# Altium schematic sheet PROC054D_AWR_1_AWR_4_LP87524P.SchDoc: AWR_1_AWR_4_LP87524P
size 558 x 431 mm; Date: Not shown in title block; ApprovedBy: Not shown in title block; CheckedBy: Not shown in title block; Author: Not shown in title block; CompanyName: Not shown in title block; DrawnBy: a0271760; Engineer: Not shown in title block; Organization: Not shown in title block; Address1: Not shown in title block; Address2: Not shown in title block; Address3: Not shown in title block; Address4: Not shown in title block; DocumentNumber: 4; Revision: Use project pAWRameter SCH_Rev; SheetNumber: 4; SheetTotal: 19; PageSetup: Record=PageOptions¦CenterHorizontal=True¦CenterVertical=True¦PrintScale=1.00¦XCorrection=1.00¦YCorrection=1.00¦PrintKind=0¦BorderSize=5000000¦LeftOffset=0¦BottomOffset=0¦Orientation=2¦PaperLength=1000¦PaperWidth=1000¦Scale=100¦PaperSource=15¦PrintQuality=600¦MediaType=1¦DitherType=10¦PaperKind=Letter¦PrintScaleMode=1
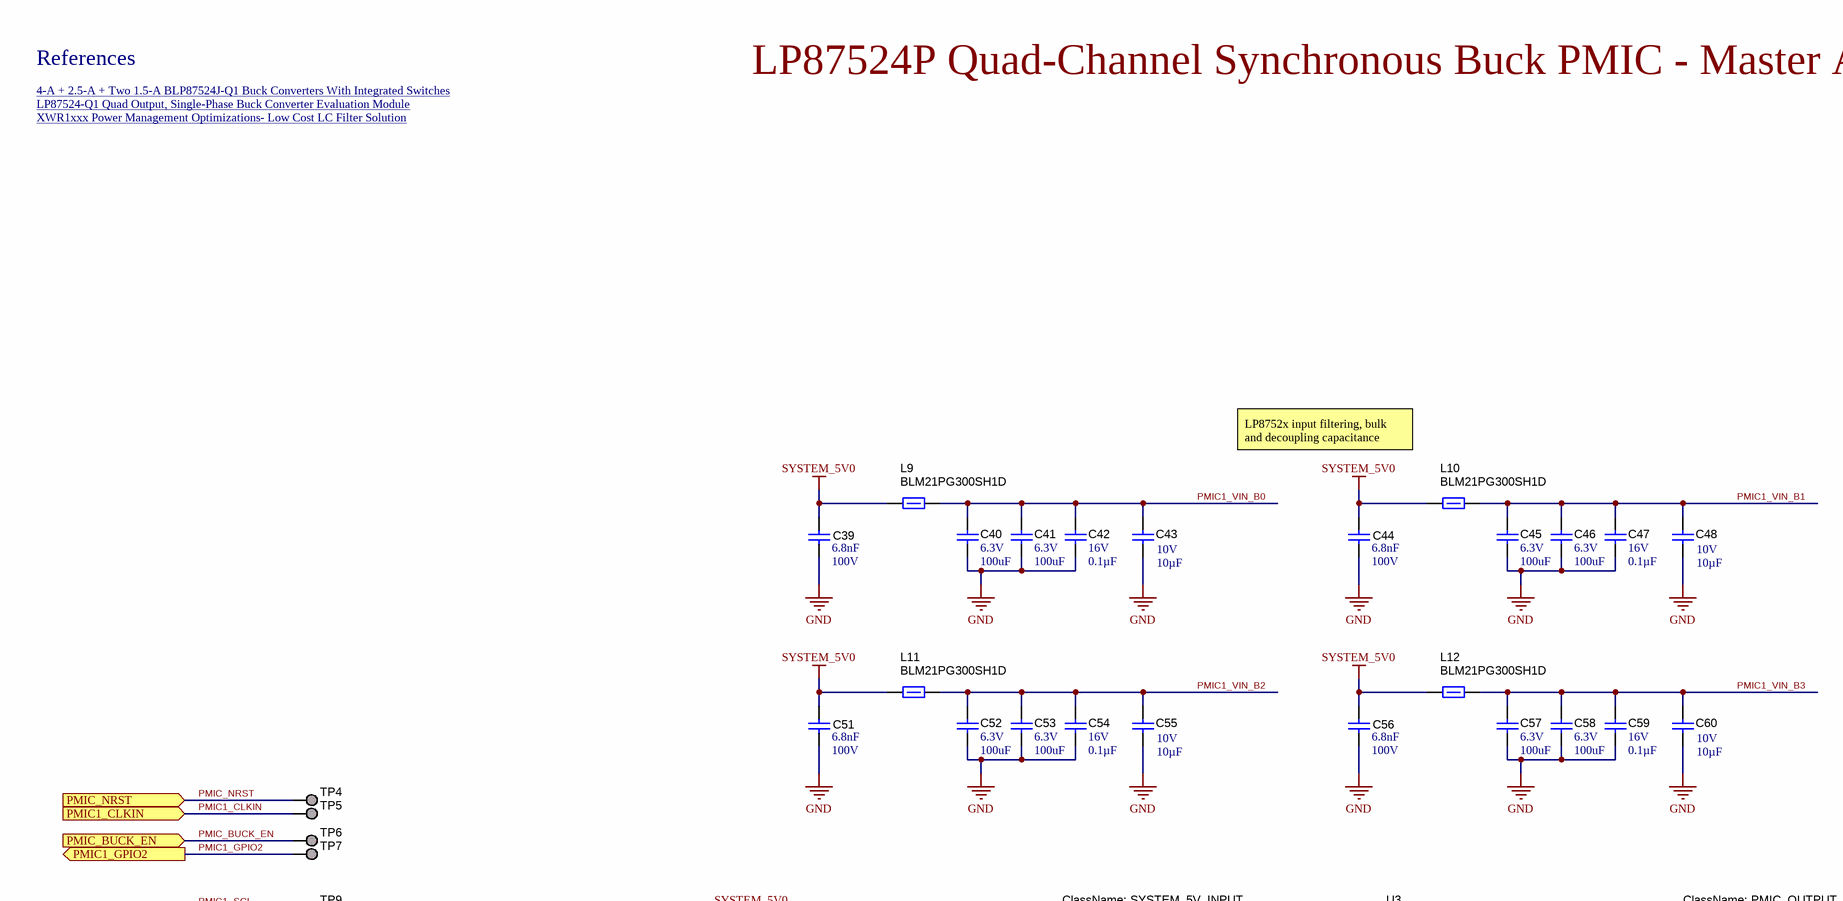
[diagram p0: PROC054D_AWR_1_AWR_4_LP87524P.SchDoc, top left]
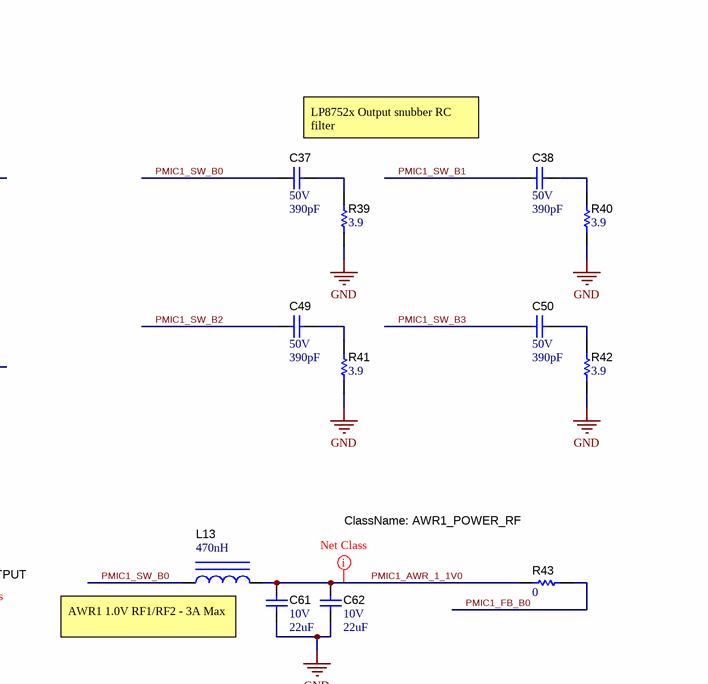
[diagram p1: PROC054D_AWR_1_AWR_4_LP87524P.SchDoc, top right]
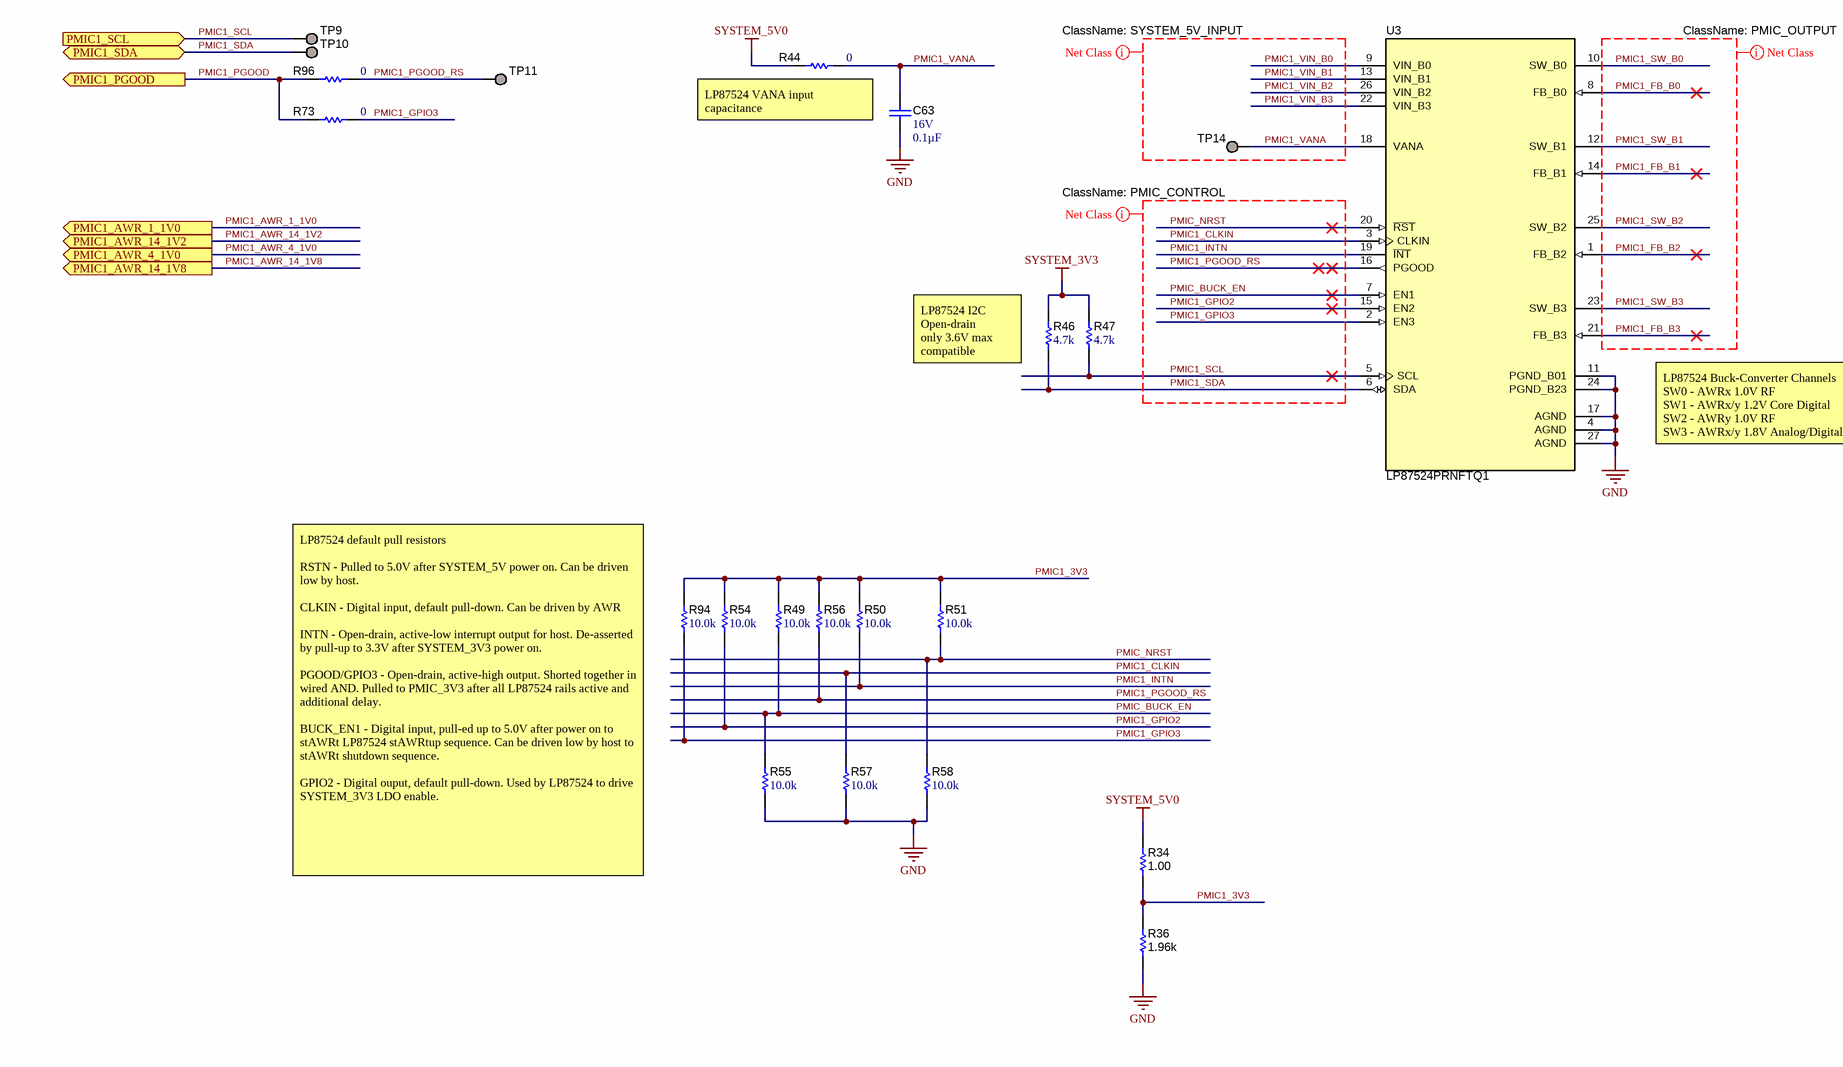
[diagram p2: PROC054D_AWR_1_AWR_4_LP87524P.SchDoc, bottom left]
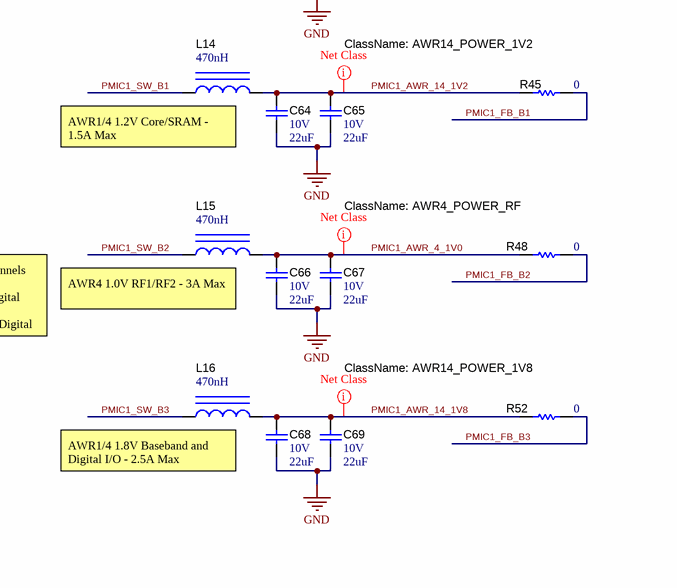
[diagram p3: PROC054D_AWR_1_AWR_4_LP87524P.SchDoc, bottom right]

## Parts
C37  VDC_V: 50V  ValueDisplayed: 390pF  [0402S]  (hidden comment: GCM155R71H391KA37D)
C38  VDC_V: 50V  ValueDisplayed: 390pF  [0402S]  (hidden comment: GCM155R71H391KA37D)
C39  Cap_F: 6.8nF  VDC_V: 100V  [0603S]  (hidden comment: GCM188R72A682KA37D)
C40  VDC_V: 6.3V  ValueDisplayed: 100uF  [0805L]  (hidden comment: GRM21BR60J107M)
C41  VDC_V: 6.3V  ValueDisplayed: 100uF  [0805L]  (hidden comment: GRM21BR60J107M)
C42  VDC_V: 16V  ValueDisplayed: 0.1µF  [0402S]  (hidden comment: GCM155R71C104JA55D)
C43  Cap_F: 10µF  VDC_V: 10V  [0805L]  (hidden comment: GRM21BR71A106KA73L)
C44  Cap_F: 6.8nF  VDC_V: 100V  [0603S]  (hidden comment: GCM188R72A682KA37D)
C45  VDC_V: 6.3V  ValueDisplayed: 100uF  [0805L]  (hidden comment: GRM21BR60J107M)
C46  VDC_V: 6.3V  ValueDisplayed: 100uF  [0805L]  (hidden comment: GRM21BR60J107M)
C47  VDC_V: 16V  ValueDisplayed: 0.1µF  [0402S]  (hidden comment: GCM155R71C104JA55D)
C48  Cap_F: 10µF  VDC_V: 10V  [0805L]  (hidden comment: GRM21BR71A106KA73L)
C49  VDC_V: 50V  ValueDisplayed: 390pF  [0402S]  (hidden comment: GCM155R71H391KA37D)
C50  VDC_V: 50V  ValueDisplayed: 390pF  [0402S]  (hidden comment: GCM155R71H391KA37D)
C51  Cap_F: 6.8nF  VDC_V: 100V  [0603S]  (hidden comment: GCM188R72A682KA37D)
C52  VDC_V: 6.3V  ValueDisplayed: 100uF  [0805L]  (hidden comment: GRM21BR60J107M)
C53  VDC_V: 6.3V  ValueDisplayed: 100uF  [0805L]  (hidden comment: GRM21BR60J107M)
C54  VDC_V: 16V  ValueDisplayed: 0.1µF  [0402S]  (hidden comment: GCM155R71C104JA55D)
C55  Cap_F: 10µF  VDC_V: 10V  [0805L]  (hidden comment: GRM21BR71A106KA73L)
C56  Cap_F: 6.8nF  VDC_V: 100V  [0603S]  (hidden comment: GCM188R72A682KA37D)
C57  VDC_V: 6.3V  ValueDisplayed: 100uF  [0805L]  (hidden comment: GRM21BR60J107M)
C58  VDC_V: 6.3V  ValueDisplayed: 100uF  [0805L]  (hidden comment: GRM21BR60J107M)
C59  VDC_V: 16V  ValueDisplayed: 0.1µF  [0402S]  (hidden comment: GCM155R71C104JA55D)
C60  Cap_F: 10µF  VDC_V: 10V  [0805L]  (hidden comment: GRM21BR71A106KA73L)
C61  VDC_V: 10V  ValueDisplayed: 22uF  [0805L]  (hidden comment: C2012X7S1A226M125AC)
C62  VDC_V: 10V  ValueDisplayed: 22uF  [0805L]  (hidden comment: C2012X7S1A226M125AC)
C63  VDC_V: 16V  ValueDisplayed: 0.1µF  [0402S]  (hidden comment: GCM155R71C104JA55D)
C64  VDC_V: 10V  ValueDisplayed: 22uF  [0805L]  (hidden comment: C2012X7S1A226M125AC)
C65  VDC_V: 10V  ValueDisplayed: 22uF  [0805L]  (hidden comment: C2012X7S1A226M125AC)
C66  VDC_V: 10V  ValueDisplayed: 22uF  [0805L]  (hidden comment: C2012X7S1A226M125AC)
C67  VDC_V: 10V  ValueDisplayed: 22uF  [0805L]  (hidden comment: C2012X7S1A226M125AC)
C68  VDC_V: 10V  ValueDisplayed: 22uF  [0805L]  (hidden comment: C2012X7S1A226M125AC)
C69  VDC_V: 10V  ValueDisplayed: 22uF  [0805L]  (hidden comment: C2012X7S1A226M125AC)
L9  BLM21PG300SH1D  [0805_HV]
L10  BLM21PG300SH1D  [0805_HV]
L11  BLM21PG300SH1D  [0805_HV]
L12  BLM21PG300SH1D  [0805_HV]
L13  ValueDisplayed: 470nH  [DFE252012P]  (hidden comment: DFE252012PD-R47M)
L14  ValueDisplayed: 470nH  [DFE252012P]  (hidden comment: DFE252012PD-R47M)
L15  ValueDisplayed: 470nH  [DFE252012P]  (hidden comment: DFE252012PD-R47M)
L16  ValueDisplayed: 470nH  [DFE252012P]  (hidden comment: DFE252012PD-R47M)
R34  ValueDisplayed: 1.00  [0603]  (hidden comment: CRCW06031R00FKEA)
R36  ValueDisplayed: 1.96k  [0603]  (hidden comment: CRCW06031K96FKEA)
R39  ValueDisplayed: 3.9  [0402S]  (hidden comment: CRCW04023R90JNED)
R40  ValueDisplayed: 3.9  [0402S]  (hidden comment: CRCW04023R90JNED)
R41  ValueDisplayed: 3.9  [0402S]  (hidden comment: CRCW04023R90JNED)
R42  ValueDisplayed: 3.9  [0402S]  (hidden comment: CRCW04023R90JNED)
R43  ValueDisplayed: 0  [0402S]  (hidden comment: CRCW04020000Z0ED)
R44  ValueDisplayed: 0  [0603S]  (hidden comment: MCT06030Z0000ZP500)
R45  ValueDisplayed: 0  [0402S]  (hidden comment: CRCW04020000Z0ED)
R46  ValueDisplayed: 4.7k  [0402]  (hidden comment: CRCW04024K70JNED)
R47  ValueDisplayed: 4.7k  [0402]  (hidden comment: CRCW04024K70JNED)
R48  ValueDisplayed: 0  [0402S]  (hidden comment: CRCW04020000Z0ED)
R49  ValueDisplayed: 10.0k  [0402]  (hidden comment: CRCW040210K0FKED)
R50  ValueDisplayed: 10.0k  [0402]  (hidden comment: CRCW040210K0FKED)
R51  ValueDisplayed: 10.0k  [0402]  (hidden comment: CRCW040210K0FKED)
R52  ValueDisplayed: 0  [0402S]  (hidden comment: CRCW04020000Z0ED)
R54  ValueDisplayed: 10.0k  [0402]  (hidden comment: CRCW040210K0FKED)
R55  ValueDisplayed: 10.0k  [0402]  (hidden comment: CRCW040210K0FKED)
R56  ValueDisplayed: 10.0k  [0402]  (hidden comment: CRCW040210K0FKED)
R57  ValueDisplayed: 10.0k  [0402]  (hidden comment: CRCW040210K0FKED)
R58  ValueDisplayed: 10.0k  [0402]  (hidden comment: CRCW040210K0FKED)
R73  ValueDisplayed: 0  [0603]  (hidden comment: MCT06030Z0000ZP500)
R94  ValueDisplayed: 10.0k  [0402]  (hidden comment: CRCW040210K0FKED)
R96  ValueDisplayed: 0  [0603]  (hidden comment: MCT06030Z0000ZP500)
TP4  TP_SM_1MM  [TP_SM_1MM]  (value not drawn)  (no BOM)
TP5  TP_SM_1MM  [TP_SM_1MM]  (value not drawn)  (no BOM)
TP6  TP_SM_1MM  [TP_SM_1MM]  (value not drawn)  (no BOM)
TP7  TP_SM_1MM  [TP_SM_1MM]  (value not drawn)  (no BOM)
TP9  TP_SM_1MM  [TP_SM_1MM]  (value not drawn)  (no BOM)
TP10  TP_SM_1MM  [TP_SM_1MM]  (value not drawn)  (no BOM)
TP11  TP_SM_1MM  [TP_SM_1MM]  (value not drawn)  (no BOM)
TP14  TP_SM_1MM  [TP_SM_1MM]  (value not drawn)  (no BOM)
U3  LP87524PRNFTQ1  [RNF0026C]

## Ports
PMIC1_AWR_1_1V0 (out), PMIC1_AWR_4_1V0 (out), PMIC1_AWR_14_1V2 (out), PMIC1_AWR_14_1V8 (out), PMIC1_CLKIN (in), PMIC1_GPIO2 (out), PMIC1_PGOOD (out), PMIC1_SCL (in), PMIC1_SDA (bidir), PMIC_BUCK_EN (in), PMIC_NRST (in)

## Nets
GND: C39.2 C40.2 C41.2 C42.2 C43.2 C44.2 C45.2 C46.2 C47.2 C48.2 C51.2 C52.2 C53.2 C54.2 C55.2 C56.2 C57.2 C58.2 C59.2 C60.2 C61.2 C62.2 C63.2 C64.2 C65.2 C66.2 C67.2 C68.2 C69.2 R36.1 R39.1 R40.1 R41.1 R42.1 R55.1 R57.1 R58.1 U3.4(AGND) U3.11(PGND_B01) U3.17(AGND) U3.24(PGND_B23) U3.27(AGND)
SYSTEM_3V3: R46.1 R47.2
SYSTEM_5V0: C39.1 C44.1 C51.1 C56.1 L9.1 L10.1 L11.1 L12.1 R34.2 R44.1
PMIC1_3V3: R34.1 R36.2 R49.2 R50.2 R51.2 R54.2 R56.2 R94.2
PMIC1_AWR_1_1V0: C61.1 C62.1 L13.2 R43.1 ; port PMIC1_AWR_1_1V0
PMIC1_AWR_4_1V0: C66.1 C67.1 L15.2 R48.1 ; port PMIC1_AWR_4_1V0
PMIC1_AWR_14_1V2: C64.1 C65.1 L14.2 R45.1 ; port PMIC1_AWR_14_1V2
PMIC1_AWR_14_1V8: C68.1 C69.1 L16.2 R52.1 ; port PMIC1_AWR_14_1V8
PMIC1_CLKIN: R57.2 TP5.1 U3.3(CLKIN) ; port PMIC1_CLKIN
PMIC1_FB_B0: R43.2 U3.8(FB_B0)
PMIC1_FB_B1: R45.2 U3.14(FB_B1)
PMIC1_FB_B2: R48.2 U3.1(FB_B2)
PMIC1_FB_B3: R52.2 U3.21(FB_B3)
PMIC1_GPIO2: R54.1 TP7.1 U3.15(EN2) ; port PMIC1_GPIO2
PMIC1_GPIO3: R73.2 R94.1 U3.2(EN3)
PMIC1_INTN: R50.1 U3.19(~{INT})
PMIC1_PGOOD: R73.1 R96.1 ; port PMIC1_PGOOD
PMIC1_PGOOD_RS: R56.1 R96.2 TP11.1 U3.16(PGOOD)
PMIC1_SCL: R47.1 TP9.1 U3.5(SCL) ; port PMIC1_SCL
PMIC1_SDA: R46.2 TP10.1 U3.6(SDA) ; port PMIC1_SDA
PMIC1_SW_B0: C37.1 L13.1 U3.10(SW_B0)
PMIC1_SW_B1: C38.1 L14.1 U3.12(SW_B1)
PMIC1_SW_B2: C49.1 L15.1 U3.25(SW_B2)
PMIC1_SW_B3: C50.1 L16.1 U3.23(SW_B3)
PMIC1_VANA: C63.1 R44.2 TP14.1 U3.18(VANA)
PMIC1_VIN_B0: C40.1 C41.1 C42.1 C43.1 L9.2 U3.9(VIN_B0)
PMIC1_VIN_B1: C45.1 C46.1 C47.1 C48.1 L10.2 U3.13(VIN_B1)
PMIC1_VIN_B2: C52.1 C53.1 C54.1 C55.1 L11.2 U3.26(VIN_B2)
PMIC1_VIN_B3: C57.1 C58.1 C59.1 C60.1 L12.2 U3.22(VIN_B3)
PMIC_BUCK_EN: R49.1 R55.2 TP6.1 U3.7(EN1) ; port PMIC_BUCK_EN
PMIC_NRST: R51.1 R58.2 TP4.1 U3.20(~{RST}) ; port PMIC_NRST
NetC37_2: C37.2 R39.2
NetC38_2: C38.2 R40.2
NetC49_2: C49.2 R41.2
NetC50_2: C50.2 R42.2

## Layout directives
net class SYSTEM_5V_INPUT: PMIC1_VANA, PMIC1_VIN_B0, PMIC1_VIN_B1, PMIC1_VIN_B2, PMIC1_VIN_B3
net class PMIC_CONTROL: PMIC1_CLKIN, PMIC1_GPIO2, PMIC1_GPIO3, PMIC1_INTN, PMIC1_PGOOD_RS, PMIC1_SCL, PMIC1_SDA, PMIC_BUCK_EN, PMIC_NRST
net class PMIC_OUTPUT: PMIC1_FB_B0, PMIC1_FB_B1, PMIC1_FB_B2, PMIC1_FB_B3, PMIC1_SW_B0, PMIC1_SW_B1, PMIC1_SW_B2, PMIC1_SW_B3
net class AWR14_POWER_1V2: PMIC1_AWR_14_1V2
net class AWR14_POWER_1V8: PMIC1_AWR_14_1V8
net class AWR1_POWER_RF: PMIC1_AWR_1_1V0
net class AWR4_POWER_RF: PMIC1_AWR_4_1V0

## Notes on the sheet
- References
- LP87524P Quad-Channel Synchronous Buck PMIC - Master AWR_1 and Slave AWR_4
- LP87524-Q1 Quad Output, Single-Phase Buck Converter Evaluation Module <http://www.ti.com/tool/lp87524q1evm>
- XWR1xxx Power Management Optimizations- Low Cost LC Filter Solution <http://www.ti.com/lit/pdf/swra577>
- 4-A + 2.5-A + Two 1.5-A BLP87524J-Q1 Buck Converters With Integrated Switches <http://www.ti.com/product/lp87524j-q1>
- LP8752x input filtering, bulk and decoupling capacitance
- (near C37) LP8752x Output snubber RC filter
- (near L13) AWR1 1.0V RF1/RF2 - 3A Max
- (near R44) LP87524 VANA input capacitance
- (near L14) AWR1/4 1.2V Core/SRAM - 1.5A Max
- (near R46) LP87524 I2C
  Open-drain
  only 3.6V max compatible
- (near L15) AWR4 1.0V RF1/RF2 - 3A Max
- LP87524 Buck-Converter Channels
  SW0 - AWRx 1.0V RF
  SW1 - AWRx/y 1.2V Core Digital
  SW2 - AWRy 1.0V RF
  SW3 - AWRx/y 1.8V Analog/Digital
- (near L16) AWR1/4 1.8V Baseband and Digital I/O - 2.5A Max
- (near R94) LP87524 default pull resistors
  RSTN - Pulled to 5.0V after SYSTEM_5V power on. Can be driven low by host.
  CLKIN - Digital input, default pull-down. Can be driven by AWR
  INTN - Open-drain, active-low interrupt output for host. De-asserted by pull-up to 3.3V after SYSTEM_3V3 power on.
  PGOOD/GPIO3 - Open-drain, active-high output. Shorted together in wired AND. Pulled to PMIC_3V3 after all LP87524 rails active and additional delay.
  BUCK_EN1 - Digital input, pull-ed up to 5.0V after power on to stAWRt LP87524 stAWRtup sequence. Can be driven low by host to stAWRt shutdown sequence.
  GPIO2 - Digital ouput, default pull-down. Used by LP87524 to drive SYSTEM_3V3 LDO enable.

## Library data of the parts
C37 C38 C49 C50 = CMP-0080703-2: CAP, CERM, 390 pF, 50 V,+/- 10%, X7R, AEC-Q200 Grade 1, 0402; Manufacturer: MuRata; Cap_Case: 0402; SizeX_mm: 1; SizeZ_mm: 0.6; SizeY_mm: 0.5; AEC Qualified: Y; Value: 390pF; Polarized: N; AEC Category: Q200; TaMax_C: 125°C; TaMin_C: -55°C; SizeAreaWB_mm2: 3; U/M: EA
C39 C44 C51 C56 = CMP-0860888-1: CAP, CERM, 6800 pF, 100 V,+/- 10%, X7R, AEC-Q200 Grade 1, 0603; Manufacturer: MuRata; AEC Grade: 1; AEC Qualified: Y; TaMin_C: -55°C; AEC Category: Q200; SizeY_mm: 0.8; Cap_Case: 0603; ValueDisplayed: 6800pF; Polarized: N; SizeArea_mm2: 1.28; U/M: EA; SizeX_mm: 1.6; SizeAreaWB_mm2: 4.68; TaMax_C: 125°C; Value: 6800pF
C40 C41 = CMP-0008280-2: CAP, CERM, 100 uF, 6.3 V, +/- 20%, X5R, 0805; Manufacturer: MuRata; TaMin_C: -55°C; Polarized: N; SizeAreaWB_mm2: 6.75; Value1: Unknown; U/M: EA; Value: 100uF; TaMax_C: 85°C; SizeZ_mm: 1.45; SizeX_mm: 2; SizeY_mm: 1.25; Cap_Case: 0805; SizeArea_mm2: 2.5; CompType: Capacitor; Cap_F: 100µF; AEC Category: Q200
C42 C63 = CMP-0080702-1: CAP, CERM, 0.1 µF, 16 V,+/- 5%, X7R, AEC-Q200 Grade 1, 0402; Manufacturer: MuRata; Cap_F: 100nF; SizeAreaWB_mm2: 3; SizeArea_mm2: 0.5; AEC Qualified: Y; AEC Category: Q200; Value: 0.1uF; TaMax_C: 125°C; SizeZ_mm: 0.6; AEC Grade: 1; Polarized: N; TaMin_C: -55°C; U/M: EA; CompType: Capacitor; Cap_Case: 0402
C43 C48 C55 C60 = CMP-0081849-1: CAP, CERM, 10 µF,  V,+/- 10%, X7R, 0805; Manufacturer: MuRata; TaMin_C: -55°C; Polarized: N; Green_Lifecycle: Active; SizeAreaWB_mm2: 6.75; Green_REACh: Passed; U/M: EA; Value: 10uF; TaMax_C: 125°C; SizeZ_mm: 1.45; SizeX_mm: 2; SizeY_mm: 1.25; Cap_Case: 0805; SizeArea_mm2: 2.5; AEC Category: Q200
C45 C46 C52 C53 C57 C58 = CMP-0008280-2: CAP, CERM, 100 uF, 6.3 V, +/- 20%, X5R, 0805; Manufacturer: MuRata; TaMin_C: -55°C; Polarized: N; SizeAreaWB_mm2: 6.75; Value1: Unknown; U/M: EA; Value: 100uF; TaMax_C: 85°C; SizeZ_mm: 1.45; SizeX_mm: 2; SizeY_mm: 1.25; Cap_Case: 0805; SizeArea_mm2: 2.5; Cap_F: 100µF; AEC Category: Q200
C47 C54 C59 = CMP-0080702-1: CAP, CERM, 0.1 µF, 16 V,+/- 5%, X7R, AEC-Q200 Grade 1, 0402; Manufacturer: MuRata; Cap_F: 100nF; SizeAreaWB_mm2: 3; SizeArea_mm2: 0.5; AEC Qualified: Y; AEC Category: Q200; Value: 0.1uF; TaMax_C: 125°C; SizeZ_mm: 0.6; AEC Grade: 1; Polarized: N; TaMin_C: -55°C; U/M: EA; Cap_Case: 0402
C61 C62 C64-C69 = CMP-0007890-1: CAP, CERM, 22 uF, 10 V, +/- 20%, X7S, 0805; Manufacturer: TDK; TaMin_C: -55°C; ESR_ohm: 2.05m; Polarized: N; SizeAreaWB_mm2: 6.75; Value1: 0.00205 ohm; U/M: EA; Value: 22uF; TaMax_C: 125°C; SizeZ_mm: 1.45; SizeX_mm: 2; SizeY_mm: 1.25; Cap_Case: 0805; SizeArea_mm2: 2.5; Cap_F: 22µF; IRMS_A: 4.5559A; AEC Category: Q200
L9-L12 = CMP-0003364-1: Ferrite Bead, 30 ohm @ 100 MHz, 4 A, 0805; Manufacturer: MuRata; ZTyp@100MHz_Ohm: 30; SizeAreaWB_mm2: 6.75; DCR_ohm: 0.014; Value1: 0.014 ohm; Value: 30 ohm; Imax_A: 4A; SizeZ_mm: 1.45; SizeX_mm: 2; SizeY_mm: 1.25; SizeArea_mm2: 2.5
L13-L16 = CMP-0058944-1: Inductor, Shielded, 470 nH, 4.7 A, 0.021 ohm, SMD; Manufacturer: MuRata Toko; Isat: 6.1A @ 30% inductance drop; Irms: 4.7A @ 40C rise; SizeAreaWB_mm2: 10.5; DCR_ohm: 0.021; Value: 470nH; Imax_A: 4.7A; SizeZ_mm: 1.2; SizeX_mm: 2.5; SizeY_mm: 2; SizeArea_mm2: 5; AEC Category: Q200
R34 = CMP-0022170-4: RES, 1.00, 1%, 0.1 W, AEC-Q200 Grade 0, 0603; Manufacturer: Vishay-Dale; Power_W: 100mW; TempCo: 100 ppm/C; Value_Code: 1R00; Value: 1.00; EIA_Code: E96; Res_ohm: 1; SizeX_mm: 1.6; SizeY_mm: 0.8; Value2: 0.1W; SizeArea_mm2: 1.28; AEC Qualified: Y; VDC_V: 75V; AEC Category: Q200; AEC Grade: 0
R36 = CMP-0022137-4: RES, 1.96 k, 1%, 0.1 W, AEC-Q200 Grade 0, 0603; Manufacturer: Vishay-Dale; Power_W: 100mW; TempCo: 100 ppm/C; Value_Code: 1k96; Value: 1.96k; EIA_Code: E96; SizeX_mm: 1.6; SizeY_mm: 0.8; SizeZ_mm: 1; Value2: 0.1W; SizeArea_mm2: 1.28; AEC Qualified: Y; VDC_V: 75V; AEC Category: Q200; AEC Grade: 0
R39 = CMP-0026928-3: RES, 3.9, 5%, 0.063 W, AEC-Q200 Grade 0, 0402; Manufacturer: Vishay-Dale; Power_W: 63mW; TempCo: 200 ppm/C; Value_Code: 3R90; Value: 3.9; EIA_Code: E24; SizeX_mm: 1; SizeY_mm: 0.5; SizeZ_mm: 0.6; Value2: 0.063W; CompType: Resistor; AEC Qualified: Y; VDC_V: 50V; AEC Category: Q200; AEC Grade: 0
R40-R42 = CMP-0026928-3: RES, 3.9, 5%, 0.063 W, AEC-Q200 Grade 0, 0402; Manufacturer: Vishay-Dale; Power_W: 63mW; TempCo: 200 ppm/C; Value_Code: 3R90; Value: 3.9; EIA_Code: E24; SizeX_mm: 1; SizeY_mm: 0.5; SizeZ_mm: 0.6; Value2: 0.063W; AEC Qualified: Y; VDC_V: 50V; AEC Category: Q200; AEC Grade: 0
R43 R45 R48 R52 = CMP-0026822-3: RES, 0, 5%, 0.063 W, AEC-Q200 Grade 0, 0402; Manufacturer: Vishay-Dale; Power_W: 63mW; TempCo: 200 ppm/C; Value_Code: 0000; Value: 0; EIA_Code: E24; SizeX_mm: 1; SizeY_mm: 0.5; SizeZ_mm: 0.6; Value2: 0.063W; AEC Qualified: Y; VDC_V: 50V; AEC Category: Q200
R44 = CMP-0025884-3: RES, 0, 5%, 0.125 W, 0603; Manufacturer: Vishay/Beyschlag; Power_W: 125mW; TempCo: ppm/C; Value_Code: 0000; U/M: EA; Value: 0; EIA_Code: E24; SizeX_mm: 1.6; SizeY_mm: 0.8; SizeZ_mm: 1; Value2: 0.125W; SizeArea_mm2: 1.28; CompType: Resistor; AEC Qualified: N; AEC Category: Q200
R46 = CMP-0026938-5: RES, 4.7 k, 5%, 0.063 W, AEC-Q200 Grade 0, 0402; Manufacturer: Vishay-Dale; Power_W: 63mW; TempCo: 200 ppm/C; Value_Code: 4k70; Value: 4.7k; EIA_Code: E24; SizeX_mm: 1; SizeY_mm: 0.5; SizeZ_mm: 0.6; Value2: 0.063W; CompType: Resistor; AEC Qualified: Y; VDC_V: 50V; AEC Category: Q200; AEC Grade: 0
R47 = CMP-0026938-5: RES, 4.7 k, 5%, 0.063 W, AEC-Q200 Grade 0, 0402; Manufacturer: Vishay-Dale; Power_W: 63mW; TempCo: 200 ppm/C; Value_Code: 4k70; Value: 4.7k; EIA_Code: E24; SizeX_mm: 1; SizeY_mm: 0.5; SizeZ_mm: 0.6; Value2: 0.063W; AEC Qualified: Y; VDC_V: 50V; AEC Category: Q200; AEC Grade: 0
R49-R51 R54-R58 R94 = CMP-0025958-3: RES, 10.0 k, 1%, 0.063 W, AEC-Q200 Grade 0, 0402; Manufacturer: Vishay-Dale; Power_W: 63mW; TempCo: 100 ppm/C; Value_Code: 10k0; Value: 10.0k; EIA_Code: E96; Res_ohm: 10k; SizeX_mm: 1; SizeY_mm: 0.5; SizeZ_mm: 0.6; Value2: 0.063W; AEC Qualified: Y; VDC_V: 50V; AEC Category: Q200; AEC Grade: 0
R73 R96 = CMP-0025884-3: RES, 0, 5%, 0.125 W, 0603; Manufacturer: Vishay/Beyschlag; Power_W: 125mW; TempCo: ppm/C; Value_Code: 0000; U/M: EA; Value: 0; EIA_Code: E24; SizeX_mm: 1.6; SizeY_mm: 0.8; SizeZ_mm: 1; Value2: 0.125W; SizeArea_mm2: 1.28; AEC Qualified: N; AEC Category: Q200
TP4-TP7 TP9-TP11 TP14 = CMP-0003825-1: 1mm Test Point, SMT; Manufacturer: Any
U3 = CMP-0083823-1: 4-A + 2.5-A + Two 1.5-A Buck Converters With Integrated Switches, RNF0026C (VQFN-HR-26); Alternate PartNumber: LP87524PRNFRQ1; Alternate Manufacturer: Texas Instruments; SizeAreaWB_mm2: 27.5; Rating: Automotive; SizeZ_mm: 0.9; SizeX_mm: 4; SizeY_mm: 4.5; SizeArea_mm2: 18; CompType: IC; AEC Qualified: Y; AEC Category: Q200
